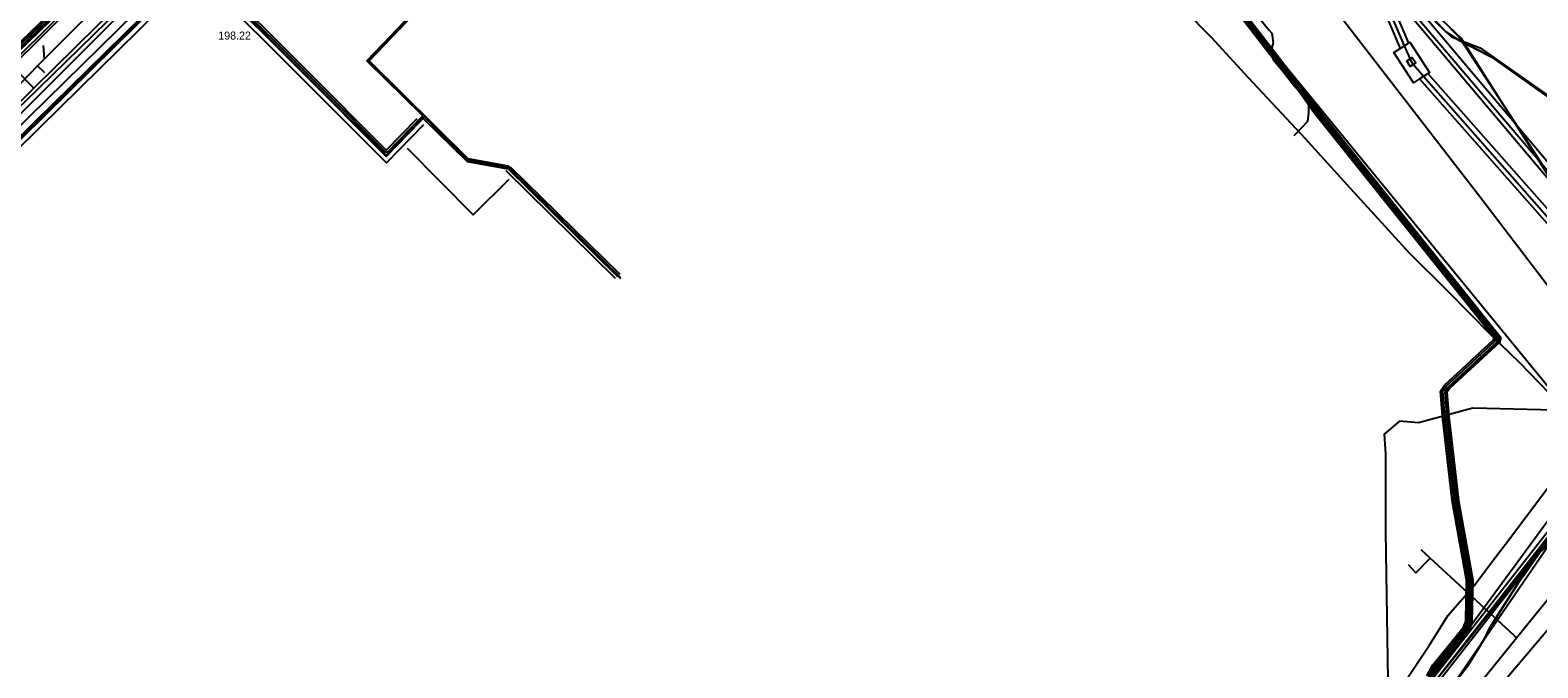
# Model space of a CAD drawing. Extents: x -598932 to -598196, y -1162210 to -1161504.
# Drawn here: x -598778.2 to -598627.1, y -1161789 to -1161725.1 of the extents above; entities that cross this region are included whole.
import ezdxf

# ---------------------------------------------------------------- set-up
doc = ezdxf.new("R2010")
doc.units = 0
for name, color, linetype in [('Vrstva 1', 7, 'Continuous'), ('Vrstva 10', 7, 'Continuous'), ('Vrstva 12', 7, 'Continuous'), ('Vrstva 14', 7, 'Continuous'), ('Vrstva 16', 7, 'Continuous'), ('Vrstva 25', 7, 'Continuous'), ('Vrstva 26', 7, 'Continuous'), ('Vrstva 29', 7, 'Continuous'), ('Vrstva 30', 7, 'Continuous'), ('Vrstva 42', 7, 'Continuous'), ('Vrstva 44', 7, 'Continuous'), ('Vrstva 53', 7, 'Continuous'), ('Vrstva 55', 7, 'Continuous'), ('Vrstva 58', 7, 'Continuous'), ('Vrstva 9', 7, 'Continuous')]:
    doc.layers.add(name, color=color, linetype=linetype)

msp = doc.modelspace()

# ---------------------------------------------------------------- linework, layer by layer
at = {"layer": 'Vrstva 1'}
msp.add_line((-598776.946, -1161726.621), (-598776.831, -1161727.99), dxfattribs=at)
at = {"layer": 'Vrstva 10'}
for p, q in [((-598649.76, -1161703.68), (-598640.1, -1161726.37)), ((-598649.76, -1161703.68), (-598640.1, -1161726.37)), ((-598650.69, -1161704.04), (-598640.95, -1161726.92)), ((-598650.69, -1161704.04), (-598640.95, -1161726.92)), ((-598649.44, -1161712.32), (-598613.14, -1161755.36)), ((-598649.44, -1161712.32), (-598613.14, -1161755.36)), ((-598648.42, -1161711.89), (-598612.32, -1161754.71)), ((-598648.42, -1161711.89), (-598612.32, -1161754.71)), ((-598640.95, -1161726.92), (-598640.1, -1161726.37)), ((-598640.95, -1161726.92), (-598640.1, -1161726.37)), ((-598639.01, -1161729.96), (-598638.16, -1161729.41)), ((-598639.01, -1161729.96), (-598638.16, -1161729.41)), ((-598638.16, -1161729.41), (-598618.46, -1161751.78)), ((-598638.16, -1161729.41), (-598618.46, -1161751.78)), ((-598639.01, -1161729.96), (-598619.23, -1161752.41)), ((-598639.01, -1161729.96), (-598619.23, -1161752.41)), ((-598639.29, -1161792.09), (-598612.59, -1161757.94)), ((-598639.29, -1161792.09), (-598612.59, -1161757.94)), ((-598638.76, -1161792.44), (-598612.09, -1161758.33)), ((-598638.76, -1161792.44), (-598612.09, -1161758.33))]:
    msp.add_line(p, q, dxfattribs=at)
for points in [[(-598640.1, -1161726.37), (-598639.98, -1161726.3), (-598638.02, -1161729.32), (-598638.16, -1161729.41)], [(-598640.1, -1161726.37), (-598639.98, -1161726.3), (-598638.02, -1161729.32), (-598638.16, -1161729.41)], [(-598639.01, -1161729.96), (-598639.62, -1161730.35), (-598641.57, -1161727.33), (-598640.95, -1161726.92)], [(-598639.01, -1161729.96), (-598639.62, -1161730.35), (-598641.57, -1161727.33), (-598640.95, -1161726.92)], [(-598640.29, -1161728.16), (-598639.74, -1161727.81), (-598639.39, -1161728.36), (-598639.94, -1161728.71), (-598640.29, -1161728.16)], [(-598640.29, -1161728.16), (-598639.74, -1161727.81), (-598639.39, -1161728.36), (-598639.94, -1161728.71), (-598640.29, -1161728.16)]]:
    msp.add_lwpolyline(points, dxfattribs=at)
at = {"layer": 'Vrstva 12'}
msp.add_line((-598611.21, -1161756.79), (-598644.24, -1161717.96), dxfattribs=at)
for points in [[(-598650.94, -1161702.19), (-598651.49, -1161703.38), (-598651.74, -1161703.91), (-598652.76, -1161706.76), (-598653.76, -1161707.91), (-598660.29, -1161714.02), (-598660.76, -1161715.17), (-598661.21, -1161715.82), (-598661.06, -1161716.45), (-598654.12, -1161725.04), (-598653.82, -1161725.38), (-598653.68, -1161726.34), (-598653.95, -1161727.3), (-598653.66, -1161728.02), (-598651.09, -1161731.11), (-598650.15, -1161732.32), (-598650.13, -1161733.36), (-598650.23, -1161734.23), (-598651.45, -1161735.5), (-598651.6, -1161735.66)], [(-598644.24, -1161717.96), (-598640.54, -1161726.66), (-598639.8, -1161728.29)], [(-598639.8, -1161728.29), (-598638.6, -1161729.7), (-598618.85, -1161752.1)], [(-598640.35, -1161794.18), (-598638.99, -1161792.25), (-598612.86, -1161758.86)], [(-598618.89, -1161765.62), (-598622.01, -1161765.47), (-598624.13, -1161763.18), (-598633.65, -1161762.95), (-598639.12, -1161764.44), (-598641.01, -1161764.25), (-598642.56, -1161765.55), (-598642.41, -1161767.52), (-598642.41, -1161775.34), (-598642.17, -1161790.19), (-598649.69, -1161797.54), (-598651.68, -1161795.52), (-598698.16, -1161842.5), (-598698.36, -1161842.27)], [(-598641.69, -1161795.86), (-598641.14, -1161794.65), (-598621.42, -1161767.75), (-598618.89, -1161765.62)]]:
    msp.add_lwpolyline(points, dxfattribs=at)
at = {"layer": 'Vrstva 14'}
for points in [[(-598763.576, -1161717.371), (-598767.793, -1161721.498), (-598778.78, -1161732.25), (-598780.042, -1161733.466)], [(-598714.198, -1161898.74), (-598714.06, -1161898.556), (-598710.961, -1161889.776), (-598709.348, -1161885.209), (-598692.94, -1161864.74), (-598688.776, -1161860.738), (-598685, -1161855.44), (-598662.12, -1161826.49), (-598647.66, -1161808.72), (-598629.293, -1161785.959), (-598621.98, -1161776.96), (-598617.208, -1161768.282), (-598616.2, -1161767.15), (-598599.603, -1161749.072), (-598591.333, -1161740.194), (-598580.26, -1161728.311)], [(-598629.293, -1161785.959), (-598629.536, -1161785.74), (-598637.938, -1161777.971), (-598638.826, -1161777.141)], [(-598637.938, -1161777.971), (-598639.388, -1161779.463), (-598640.123, -1161778.666)]]:
    msp.add_lwpolyline(points, dxfattribs=at)
at = {"layer": 'Vrstva 16'}
for points in [[(-598805.94, -1161758.5), (-598800, -1161752.76), (-598795.62, -1161748.68), (-598777.88, -1161730.9), (-598767.37, -1161720.52), (-598763.52, -1161716.69)], [(-598777.88, -1161730.9), (-598782.7, -1161726.02), (-598785.29, -1161723.4)]]:
    msp.add_lwpolyline(points, dxfattribs=at)
at = {"layer": 'Vrstva 25'}
msp.add_line((-598730.342, -1161738.978), (-598719.372, -1161749.756), dxfattribs=at)
for points in [[(-598763.58, -1161720.316), (-598777.802, -1161734.301), (-598795.423, -1161751.633), (-598804.628, -1161760.78), (-598810.559, -1161754.845)], [(-598763.58, -1161720.316), (-598761.671, -1161722.17), (-598759.867, -1161720.402), (-598751.073, -1161729.207), (-598742.551, -1161737.734), (-598739.148, -1161734.249)], [(-598739.148, -1161734.249), (-598738.843, -1161733.929), (-598734.454, -1161738.241), (-598730.342, -1161738.978)]]:
    msp.add_lwpolyline(points, dxfattribs=at)
at = {"layer": 'Vrstva 26'}
for p, q in [((-598719.582, -1161749.97), (-598730.553, -1161739.192)), ((-598730.132, -1161738.764), (-598719.162, -1161749.542))]:
    msp.add_line(p, q, dxfattribs=at)
for points in [[(-598810.029, -1161754.315), (-598804.626, -1161759.721), (-598795.95, -1161751.1), (-598778.328, -1161733.766), (-598764.106, -1161719.781)], [(-598762.724, -1161720.52), (-598761.672, -1161721.541), (-598759.864, -1161719.769), (-598750.755, -1161728.889), (-598742.555, -1161737.094), (-598739.47, -1161733.934)], [(-598763.363, -1161721.154), (-598777.276, -1161734.835), (-598794.895, -1161752.166), (-598804.63, -1161761.84), (-598811.09, -1161755.376)], [(-598738.826, -1161734.563), (-598742.547, -1161738.375), (-598751.391, -1161729.525), (-598759.87, -1161721.036), (-598761.67, -1161722.798), (-598763.363, -1161721.154)]]:
    msp.add_lwpolyline(points, dxfattribs=at)
at = {"layer": 'Vrstva 29'}
msp.add_lwpolyline([(-598740.472, -1161736.905), (-598733.856, -1161743.594), (-598730.244, -1161740.022)], dxfattribs=at)
at = {"layer": 'Vrstva 30'}
for points in [[(-598810.719, -1161754.936), (-598804.637, -1161761.054), (-598762.81, -1161719.841), (-598762.788, -1161717.399), (-598767.899, -1161712.396), (-598767.879, -1161710.078), (-598760.022, -1161702.127), (-598776.989, -1161685.334), (-598759.185, -1161668.036), (-598729.249, -1161638.446), (-598724.611, -1161639.58), (-598721.696, -1161630.609), (-598719.628, -1161625.122), (-598725.779, -1161622.994), (-598747.341, -1161645.193), (-598747.571, -1161645.193), (-598767.228, -1161625.719), (-598767.595, -1161625.719), (-598779.142, -1161637.747), (-598797.512, -1161631.089), (-598803.541, -1161629.179), (-598806.355, -1161636.247), (-598810.188, -1161635.203), (-598811.825, -1161639.792)], [(-598820.222, -1161744.665), (-598811.82, -1161735.679), (-598818.744, -1161728.441), (-598809.235, -1161719.225), (-598790.863, -1161701.315), (-598777.544, -1161688.533), (-598776.151, -1161689.91), (-598774.559, -1161688.361), (-598760.6, -1161702.173), (-598768.357, -1161710.094), (-598768.357, -1161712.366), (-598763.251, -1161717.417), (-598763.251, -1161719.756), (-598763.613, -1161720.068), (-598761.683, -1161721.926), (-598759.897, -1161720.244), (-598750.651, -1161729.513), (-598742.552, -1161737.617), (-598738.771, -1161733.774), (-598734.4, -1161738.092), (-598730.43, -1161738.809), (-598719.083, -1161749.96)], [(-598736.156, -1161719.415), (-598744.506, -1161728.161), (-598738.949, -1161733.59), (-598738.949, -1161733.738), (-598742.441, -1161737.306), (-598742.64, -1161737.306), (-598748.758, -1161731.159), (-598759.841, -1161720.081), (-598761.672, -1161721.799), (-598763.331, -1161720.203), (-598804.632, -1161760.913), (-598810.651, -1161754.895)], [(-598719.046, -1161749.906), (-598730.17, -1161738.978), (-598730.141, -1161738.864), (-598730.3, -1161738.708), (-598734.336, -1161737.98), (-598744.285, -1161728.164), (-598736.057, -1161719.531)]]:
    msp.add_lwpolyline(points, dxfattribs=at)
at = {"layer": 'Vrstva 42'}
msp.add_line((-598640.42, -1161794.02), (-598611.08, -1161757.27), dxfattribs=at)
for points in [[(-598810.719, -1161754.936), (-598804.637, -1161761.054), (-598762.81, -1161719.841), (-598762.788, -1161717.399), (-598767.899, -1161712.396), (-598767.879, -1161710.078), (-598760.022, -1161702.127), (-598776.989, -1161685.334), (-598759.185, -1161668.036), (-598729.249, -1161638.446), (-598724.611, -1161639.58), (-598721.696, -1161630.609), (-598719.628, -1161625.122), (-598725.779, -1161622.994), (-598747.341, -1161645.193), (-598747.571, -1161645.193), (-598767.228, -1161625.719), (-598767.595, -1161625.719), (-598779.142, -1161637.747), (-598797.512, -1161631.089), (-598803.541, -1161629.179), (-598806.355, -1161636.247), (-598810.188, -1161635.203), (-598811.825, -1161639.792)], [(-598820.222, -1161744.665), (-598811.82, -1161735.679), (-598818.744, -1161728.441), (-598809.235, -1161719.225), (-598790.863, -1161701.315), (-598777.544, -1161688.533), (-598776.151, -1161689.91), (-598774.559, -1161688.361), (-598760.6, -1161702.173), (-598768.357, -1161710.094), (-598768.357, -1161712.366), (-598763.251, -1161717.417), (-598763.251, -1161719.756), (-598763.613, -1161720.068), (-598761.683, -1161721.926), (-598759.897, -1161720.244), (-598750.651, -1161729.513), (-598742.552, -1161737.617), (-598738.771, -1161733.774), (-598734.4, -1161738.092), (-598730.43, -1161738.809), (-598719.083, -1161749.96)], [(-598736.156, -1161719.415), (-598744.506, -1161728.161), (-598738.949, -1161733.59), (-598738.949, -1161733.738), (-598742.441, -1161737.306), (-598742.64, -1161737.306), (-598748.758, -1161731.159), (-598759.841, -1161720.081), (-598761.672, -1161721.799), (-598763.331, -1161720.203), (-598804.632, -1161760.913), (-598810.651, -1161754.895)], [(-598719.046, -1161749.906), (-598730.17, -1161738.978), (-598730.141, -1161738.864), (-598730.3, -1161738.708), (-598734.336, -1161737.98), (-598744.285, -1161728.164), (-598736.057, -1161719.531)]]:
    msp.add_lwpolyline(points, dxfattribs=at)
at = {"layer": 'Vrstva 44'}
for points in [[(-598780.563, -1161728.042), (-598770.209, -1161717.988), (-598767.1, -1161715.029), (-598765.11, -1161713.009), (-598760.727, -1161708.746), (-598759.9, -1161707.52), (-598757.753, -1161704.945), (-598757.516, -1161703.76), (-598757.124, -1161702.843), (-598752.29, -1161698.029), (-598741.24, -1161687.349), (-598734.04, -1161680.219), (-598725.58, -1161671.819), (-598709.44, -1161655.908), (-598707.221, -1161653.8), (-598706.621, -1161653.159), (-598705.462, -1161652.081), (-598705.002, -1161651.54), (-598704.027, -1161650.674), (-598703.75, -1161649.767), (-598703.779, -1161648.886), (-598704.437, -1161647.65), (-598704.541, -1161646.665)], [(-598780.417, -1161728.178), (-598770.071, -1161718.132), (-598766.96, -1161715.171), (-598764.97, -1161713.151), (-598760.573, -1161708.874), (-598759.74, -1161707.64), (-598757.567, -1161705.035), (-598757.324, -1161703.82), (-598756.956, -1161702.957), (-598752.15, -1161698.171), (-598741.1, -1161687.491), (-598733.9, -1161680.361), (-598725.44, -1161671.961), (-598709.3, -1161656.052), (-598707.079, -1161653.94), (-598706.479, -1161653.301), (-598705.318, -1161652.219), (-598704.858, -1161651.68), (-598703.853, -1161650.786), (-598703.55, -1161649.793), (-598703.581, -1161648.834), (-598704.243, -1161647.59), (-598704.34, -1161646.676)], [(-598625.08, -1161762.41), (-598628.94, -1161758.4), (-598631.84, -1161755.65), (-598636.17, -1161751.25), (-598640, -1161747.44), (-598645.92, -1161740.95), (-598650.45, -1161735.97), (-598656.14, -1161729.87), (-598659.84, -1161725.82), (-598662.66, -1161722.99), (-598665.44, -1161720.12), (-598665.62, -1161719.89), (-598666.1, -1161719.82), (-598666.46, -1161719.76)], [(-598642.7, -1161793.69), (-598637.97, -1161786.62), (-598636.14, -1161783.68), (-598633.49, -1161780.69), (-598631.58, -1161778.16), (-598629.97, -1161776.02), (-598625.78, -1161770.44)]]:
    msp.add_lwpolyline(points, dxfattribs=at)
at = {"layer": 'Vrstva 53'}
for points in [[(-598667.25, -1161680.15), (-598666.75, -1161681.51), (-598666, -1161683.15), (-598661.6, -1161691.91), (-598657.44, -1161698.91), (-598656.02, -1161700.51), (-598646.84, -1161708.05), (-598644.85, -1161713.63), (-598644.46, -1161714.82), (-598643.28, -1161717.76), (-598642.4, -1161718.82), (-598637.25, -1161724.42), (-598635.79, -1161725.75), (-598632.93, -1161726.87), (-598631.008, -1161728.217)], [(-598631.008, -1161728.217), (-598622.71, -1161734.03), (-598615.07, -1161739.76), (-598611.49, -1161743.17), (-598609.61, -1161747.61)], [(-598609.841, -1161749.701), (-598612.07, -1161752.18), (-598612.85, -1161753.03), (-598613.52, -1161753.62), (-598623.35, -1161763.72), (-598623.69, -1161765.36), (-598623.39, -1161766.52), (-598623.11, -1161769.13), (-598622.73, -1161770.39), (-598622.65, -1161771.79), (-598625.03, -1161775.74), (-598626.92, -1161777.34), (-598629.01, -1161780.33), (-598632.04, -1161785.05), (-598632.43, -1161785.95), (-598634.19, -1161788.81), (-598640.81, -1161797.29)]]:
    msp.add_lwpolyline(points, dxfattribs=at)
at = {"layer": 'Vrstva 55'}
for points in [[(-598687.9, -1161859.88), (-598687.665, -1161860.067), (-598686.34, -1161858.55), (-598665.36, -1161832.2), (-598647.88, -1161811.69), (-598632.26, -1161792.34), (-598620.6, -1161778.58), (-598617.8, -1161769.72), (-598610.34, -1161759), (-598610.34, -1161755.27), (-598623.936, -1161743.039), (-598634.82, -1161725.89), (-598648.11, -1161713.3), (-598648.437, -1161712.771), (-598653, -1161709.34), (-598656.27, -1161705.61), (-598668.62, -1161681.83), (-598671.66, -1161674.83), (-598683.11, -1161642.61), (-598670.09, -1161637.1), (-598667.406, -1161636.169), (-598667.557, -1161635.626)], [(-598593.724, -1161815.599), (-598601.79, -1161825.2), (-598612.66, -1161816.58), (-598614.54, -1161818.45), (-598638.67, -1161800.34), (-598641.16, -1161798.68), (-598621.91, -1161770.62), (-598621.41, -1161768.96), (-598621.41, -1161767.63), (-598621.91, -1161765.97), (-598661.59, -1161717.49), (-598653.12, -1161709.36), (-598656.44, -1161705.37), (-598668.39, -1161682.46), (-598671.71, -1161674.66), (-598683.11, -1161642.61), (-598670.09, -1161637.1), (-598667.406, -1161636.169), (-598667.557, -1161635.626)], [(-598667.557, -1161635.626), (-598667.406, -1161636.169), (-598670.09, -1161637.1), (-598683, -1161642.29), (-598671.71, -1161674.5), (-598668.55, -1161682.47), (-598656.43, -1161705.38), (-598652.95, -1161709.2), (-598642.32, -1161718.33), (-598635.02, -1161725.8), (-598623.513, -1161743.463)], [(-598798.79, -1161747), (-598773.75, -1161722.08), (-598766.93, -1161715.53), (-598766.48, -1161713.62), (-598760.48, -1161707.49), (-598760.34, -1161704.89), (-598753.57, -1161696.12), (-598753.47, -1161697.17)]]:
    msp.add_lwpolyline(points, dxfattribs=at)
at = {"layer": 'Vrstva 58'}
for p, q in [((-598636.451, -1161725.183), (-598639.706, -1161721.656)), ((-598637.546, -1161723.997), (-598636.38, -1161725.26)), ((-598636.38, -1161725.26), (-598636.451, -1161725.183)), ((-598636.451, -1161725.183), (-598636.13, -1161725.418)), ((-598635.07, -1161726.09), (-598636.13, -1161725.418)), ((-598636.13, -1161725.418), (-598635.07, -1161726.09)), ((-598631.912, -1161727.702), (-598635.07, -1161726.09)), ((-598635.07, -1161726.09), (-598633.891, -1161726.692)), ((-598633.535, -1161726.874), (-598631.7, -1161727.81)), ((-598631.7, -1161727.81), (-598631.898, -1161727.709)), ((-598627.966, -1161730.458), (-598631.7, -1161727.81)), ((-598631.7, -1161727.81), (-598629.465, -1161729.396)), ((-598629.452, -1161729.405), (-598627.64, -1161730.69)), ((-598623.725, -1161733.467), (-598627.64, -1161730.69)), ((-598627.64, -1161730.69), (-598625.537, -1161732.182)), ((-598628.535, -1161779.651), (-598626.92, -1161777.34)), ((-598626.92, -1161777.34), (-598627.263, -1161777.831)), ((-598627.492, -1161778.158), (-598629.01, -1161780.33)), ((-598631.164, -1161783.686), (-598629.01, -1161780.33)), ((-598629.01, -1161780.33), (-598630.172, -1161782.14)), ((-598629.01, -1161780.33), (-598628.545, -1161779.664)), ((-598630.18, -1161782.153), (-598632.04, -1161785.05)), ((-598632.43, -1161785.95), (-598632.04, -1161785.05)), ((-598632.04, -1161785.05), (-598632.43, -1161785.95)), ((-598632.04, -1161785.05), (-598631.38, -1161784.022)), ((-598632.837, -1161786.612), (-598633.8, -1161788.176)), ((-598633.792, -1161788.162), (-598632.43, -1161785.95)), ((-598632.43, -1161785.95), (-598632.627, -1161786.271)), ((-598634.19, -1161788.81), (-598633.8, -1161788.176)), ((-598633.8, -1161788.176), (-598634.19, -1161788.81)), ((-598636.686, -1161792.007), (-598634.19, -1161788.81)), ((-598634.19, -1161788.81), (-598635.555, -1161790.559))]:
    msp.add_line(p, q, dxfattribs=at)
for points in [[(-598619.66, -1161736.35), (-598631.7, -1161727.81), (-598635.07, -1161726.09), (-598636.38, -1161725.26), (-598642.85, -1161718.25), (-598643.151, -1161717.753), (-598643.83, -1161716.63), (-598646.54, -1161708.93), (-598647.69, -1161707.44), (-598650.473, -1161705.387), (-598651.81, -1161704.4), (-598655.12, -1161701.93), (-598657.18, -1161699.85), (-598662.73, -1161690.33), (-598662.865, -1161690.052), (-598664.963, -1161685.735), (-598667.08, -1161681.38), (-598670.39, -1161672.57), (-598673.45, -1161663.73), (-598673.946, -1161662.167), (-598677.89, -1161649.75), (-598678.414, -1161648.041)], [(-598709.89, -1161655.98), (-598710.83, -1161656.95), (-598718.26, -1161664.31), (-598727.24, -1161673.25), (-598736.15, -1161681.94), (-598745.23, -1161691.04), (-598752.52, -1161698.38), (-598752.88, -1161698.72), (-598759.81, -1161706.09), (-598760.38, -1161707.72), (-598765.21, -1161712.71), (-598767.68, -1161715.31), (-598769.3, -1161717), (-598773.03, -1161720.59), (-598779.68, -1161726.88), (-598787.1, -1161734.11), (-598794.69, -1161741.52), (-598801.25, -1161748.5), (-598812.82, -1161758.59), (-598813.89, -1161758.68), (-598815.57, -1161757.946)], [(-598663.406, -1161715.023), (-598663.127, -1161715.137), (-598662.071, -1161716.716), (-598660.925, -1161718.002), (-598660.861, -1161718.074), (-598658.642, -1161720.266), (-598658.419, -1161720.623), (-598658.082, -1161721.575), (-598657.571, -1161722.259), (-598651.326, -1161730.343), (-598650.803, -1161730.936), (-598649.27, -1161733.1), (-598631.089, -1161755.826), (-598631.234, -1161756.319), (-598636.206, -1161760.92), (-598636.485, -1161761.352), (-598636.261, -1161764.129), (-598636.202, -1161764.575), (-598635.332, -1161772.161), (-598633.91, -1161780.154), (-598633.981, -1161784.355), (-598634.232, -1161785.089), (-598637.334, -1161788.892), (-598637.929, -1161789.974)], [(-598767.91, -1161716.54), (-598777.5, -1161726.18), (-598781.8, -1161730.36)], [(-598780.813, -1161727.79), (-598770.41, -1161717.727)], [(-598780.67, -1161727.93), (-598770.27, -1161717.87)], [(-598780.527, -1161728.07), (-598770.13, -1161718.013)], [(-598780.527, -1161728.07), (-598770.13, -1161718.013)], [(-598619.66, -1161736.35), (-598631.7, -1161727.81), (-598635.07, -1161726.09), (-598636.38, -1161725.26), (-598642.85, -1161718.25)], [(-598619.66, -1161736.35), (-598631.7, -1161727.81), (-598635.07, -1161726.09), (-598636.38, -1161725.26), (-598642.85, -1161718.25)], [(-598642.85, -1161718.25), (-598636.38, -1161725.26), (-598636.451, -1161725.183), (-598636.13, -1161725.418), (-598635.07, -1161726.09), (-598631.7, -1161727.81), (-598627.64, -1161730.69), (-598623.712, -1161733.476)], [(-598638.271, -1161789.766), (-598637.666, -1161788.668), (-598634.588, -1161784.891), (-598634.379, -1161784.285), (-598634.31, -1161780.186), (-598635.728, -1161772.219), (-598636.598, -1161764.625), (-598636.659, -1161764.171), (-598636.895, -1161761.248), (-598636.514, -1161760.66), (-598631.586, -1161756.101), (-598631.531, -1161755.914), (-598649.59, -1161733.34), (-598651.117, -1161731.184), (-598651.634, -1161730.597), (-598657.889, -1161722.501)], [(-598631.31, -1161755.87), (-598649.43, -1161733.22), (-598650.96, -1161731.06), (-598651.48, -1161730.47), (-598657.73, -1161722.38)], [(-598657.73, -1161722.38), (-598651.48, -1161730.47), (-598650.96, -1161731.06), (-598649.43, -1161733.22), (-598631.31, -1161755.87), (-598631.41, -1161756.21), (-598636.36, -1161760.79), (-598636.69, -1161761.3), (-598636.46, -1161764.15), (-598636.4, -1161764.6), (-598635.53, -1161772.19), (-598634.11, -1161780.17), (-598634.18, -1161784.32), (-598634.41, -1161784.99), (-598636.402, -1161787.434), (-598637.5, -1161788.78), (-598638.1, -1161789.87)], [(-598657.493, -1161722.2), (-598651.25, -1161730.281), (-598650.726, -1161730.875), (-598649.192, -1161733.041), (-598630.981, -1161755.805), (-598631.148, -1161756.373), (-598636.13, -1161760.983), (-598636.385, -1161761.377), (-598636.164, -1161764.119), (-598636.105, -1161764.563), (-598635.235, -1161772.147), (-598633.812, -1161780.146), (-598633.883, -1161784.372), (-598634.145, -1161785.137), (-598637.252, -1161788.947), (-598637.845, -1161790.025)], [(-598657.342, -1161722.305), (-598651.097, -1161730.389), (-598650.574, -1161730.982), (-598649.041, -1161733.146), (-598630.86, -1161755.872), (-598631.005, -1161756.365), (-598635.977, -1161760.966), (-598636.256, -1161761.398), (-598636.032, -1161764.175), (-598635.973, -1161764.621), (-598635.103, -1161772.207), (-598633.681, -1161780.2), (-598633.752, -1161784.401), (-598634.003, -1161785.135), (-598637.105, -1161788.938), (-598637.7, -1161790.02)], [(-598638.1, -1161789.87), (-598637.5, -1161788.78), (-598636.402, -1161787.434), (-598634.41, -1161784.99), (-598634.18, -1161784.32), (-598634.11, -1161780.17), (-598635.53, -1161772.19), (-598636.4, -1161764.6), (-598636.46, -1161764.15), (-598636.69, -1161761.3), (-598636.36, -1161760.79), (-598631.41, -1161756.21), (-598631.31, -1161755.87)], [(-598669.89, -1161829.37), (-598668.06, -1161829.56), (-598667.17, -1161828.81), (-598664.51, -1161824.98), (-598658.48, -1161816.94), (-598652.34, -1161809.41), (-598646.32, -1161801.61), (-598643.47, -1161798.47), (-598640.81, -1161797.29), (-598634.19, -1161788.81), (-598632.43, -1161785.95), (-598632.04, -1161785.05), (-598629.01, -1161780.33), (-598626.92, -1161777.34), (-598625.03, -1161775.74), (-598622.65, -1161771.79), (-598622.73, -1161770.39), (-598623.11, -1161769.13), (-598623.39, -1161766.52), (-598623.69, -1161765.36)], [(-598640.81, -1161797.29), (-598634.19, -1161788.81), (-598632.43, -1161785.95), (-598632.04, -1161785.05), (-598629.01, -1161780.33), (-598626.92, -1161777.34), (-598625.03, -1161775.74), (-598622.65, -1161771.79), (-598622.73, -1161770.39), (-598623.11, -1161769.13), (-598623.39, -1161766.52), (-598623.69, -1161765.36)], [(-598636.932, -1161792.322), (-598634.19, -1161788.81), (-598632.43, -1161785.95), (-598632.04, -1161785.05), (-598631.38, -1161784.022), (-598629.01, -1161780.33), (-598628.535, -1161779.651), (-598626.92, -1161777.34)], [(-598626.92, -1161777.34), (-598629.01, -1161780.33), (-598632.04, -1161785.05), (-598632.43, -1161785.95)], [(-598632.43, -1161785.95), (-598633.8, -1161788.176), (-598634.19, -1161788.81), (-598636.932, -1161792.322)]]:
    msp.add_lwpolyline(points, dxfattribs=at)
at = {"layer": 'Vrstva 9'}
for p, q in [((-598664.02, -1161701.48), (-598632.98, -1161741.74)), ((-598764.099, -1161718.349), (-598814.706, -1161768.957)), ((-598776.79, -1161729.368), (-598777.5, -1161728.664)), ((-598632.98, -1161741.74), (-598613.88, -1161766.79))]:
    msp.add_line(p, q, dxfattribs=at)
msp.add_lwpolyline([(-598754.577, -1161705.527), (-598769.273, -1161720.36), (-598776.831, -1161727.99), (-598777.5, -1161728.664), (-598783.329, -1161734.672)], dxfattribs=at)

# ---------------------------------------------------------------- texts
at = {"layer": 'Vrstva 12'}
msp.add_text('198.22', height=0.8, dxfattribs=at).set_placement((-598759.394, -1161726.022))

doc.saveas('drawing.dxf')
